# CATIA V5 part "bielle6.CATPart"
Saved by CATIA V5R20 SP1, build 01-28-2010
Part number: bielle6
Bounding box of the stored display mesh (mm): x -185.739 to -126.739, y 0 to 10, z 68.093 to 81.907
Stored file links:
  E:\EDELI\gcausse\Edeli_2012_184_gcausse\bielle6.CATPart
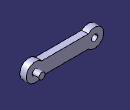
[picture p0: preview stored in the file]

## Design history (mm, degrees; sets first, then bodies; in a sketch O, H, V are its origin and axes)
Body1 (main body)
  Sketch1 on zx-plane, origin (0, 0, 0), H (-1, 0, 0), V (0, 0, 1)
    line L1 (173.84, 80) -> (138.638, 80)
    line L2 (173.84, 70) -> (138.638, 70)
    arc A1 centre (178.739, 75) radius 7 from (173.84, 80) to (173.84, 70) cw
    point P5 (178.739, 75)
    point P6 (183.638, 70)
    arc A2 centre (133.739, 75) radius 7 from (138.638, 80) to (138.638, 70) ccw
    point P7 (133.739, 75)
    circle A3 centre (178.739, 75) radius 2.5
    radius A2 = 7
    radius A1 = 7
    distance L1 L2 = 10
    distance P7 L1 = 5
    distance P5 L1 = 5
    distance P7 P5 = 45
    radius A3 = 2.5
    horizontal: L1 H, L2 H
    coincidence: A1 P6, P6 L2
  Pad1: profile Sketch1, direction (0, 1, 0), length 5
  Sketch2 on end face of Pad1, origin (0, 5, 0), H (-1, 0, 0), V (0, 0, 1)
    circle A1 centre (133.739, 75) radius 2.5
    reference projected arc E1 centre (133.739, 75) radius 7 from (138.638, 80) to (138.638, 70) ccw from edge [face of Pad1 from Sketch1.A2 | end face of Pad1]
    reference projected arc E2 centre (133.739, 75) radius 7 from (138.638, 80) to (138.638, 70) ccw from edge [face of Pad1 from Sketch1.A2 | end face of Pad1]
    radius A1 = 2.5
    radius E2 = 7 (reference)
    concentricity: A1 E1
  Pad2: profile Sketch2, direction (0, 1, 0), length 5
